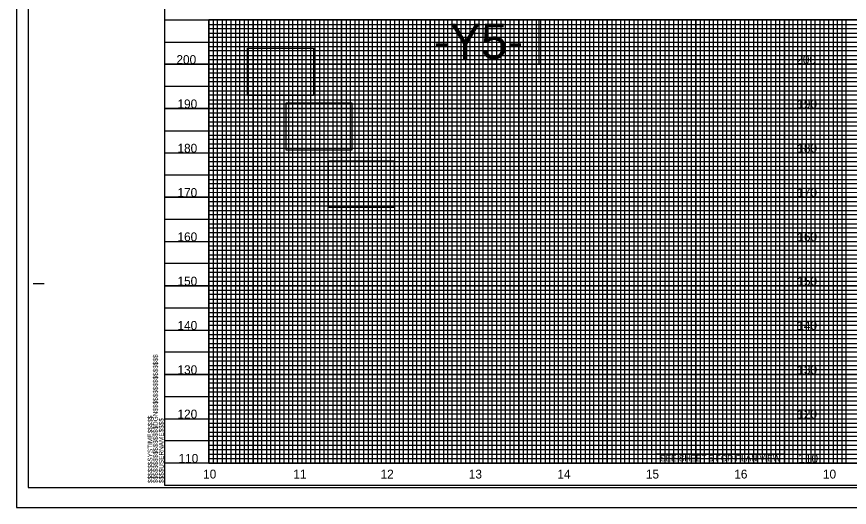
# Model space of a CAD drawing. Extents: x 1779926 to 1781626, y 618464 to 619564.
# Drawn here: x 1779926 to 1780866, y 618464 to 619018 of the extents above; entities that cross this region are included whole.
import ezdxf

# ---------------------------------------------------------------- set-up
doc = ezdxf.new("R2010")
doc.units = 0
for name, color, linetype in [('Exist Vertical Profile Horizontal Axis Label Major', 7, 'Continuous'), ('Exist Vertical Profile Vertical Axis Label', 7, 'Continuous'), ('Prop DSN Text', 7, 'Continuous'), ('Prop Grid Mask', 7, 'Continuous'), ('Sheet DOT Grid CELL', 7, 'Continuous'), ('Sheet Layout Profile Border Port 2', 7, 'Continuous'), ('Sheet Plot Border Inside CELL', 7, 'Continuous'), ('Sheet Plot Border Outside CELL', 7, 'Continuous'), ('Sheet Profile CELL', 7, 'Continuous'), ('Sheet Profile Grid Major CELL', 7, 'Continuous'), ('Sheet Profile Grid Middle CELL', 7, 'Continuous'), ('Sheet Profile Grid Minor CELL', 7, 'Continuous')]:
    doc.layers.add(name, color=color, linetype=linetype)

msp = doc.modelspace()

# ---------------------------------------------------------------- linework, layer by layer
at = {"layer": 'Prop Grid Mask'}
for points in [[(1780516.03, 619014.19), (1780393.09, 619014.19), (1780393.09, 618964.19), (1780516.03, 618964.19)], [(1780792.96, 619014.19), (1780842.96, 619014.19), (1780842.96, 618514.19), (1780792.96, 618514.19)], [(1780186.83, 618982.35), (1780261.08, 618982.35), (1780261.08, 618928.78), (1780186.83, 618928.78)], [(1780230.36, 618920.62), (1780304.61, 618920.62), (1780304.61, 618867.04), (1780230.36, 618867.04)], [(1780278.13, 618855.26), (1780352.38, 618855.26), (1780352.38, 618802.59), (1780278.13, 618802.59)], [(1780792.96, 618524.19), (1780647.96, 618524.19), (1780647.96, 618514.19), (1780792.96, 618514.19)]]:
    msp.add_lwpolyline(points, close=True, dxfattribs=at)
at = {"layer": 'Sheet DOT Grid CELL'}
for p, q in [((1780092.96, 619014.19), (1781592.85, 619014.19)), ((1780142.96, 619014.19), (1780142.96, 618514.19)), ((1780192.96, 619014.19), (1780192.96, 618514.19)), ((1780242.96, 619014.19), (1780242.96, 618514.19)), ((1780292.96, 619014.19), (1780292.96, 618514.19)), ((1780342.96, 619014.19), (1780342.96, 618514.19)), ((1780392.96, 619014.19), (1780392.96, 618514.19)), ((1780442.96, 619014.19), (1780442.96, 618514.19)), ((1780492.96, 619014.19), (1780492.96, 618514.19)), ((1780542.96, 619014.19), (1780542.96, 618514.19)), ((1780592.96, 619014.19), (1780592.96, 618514.19)), ((1780642.96, 619014.19), (1780642.96, 618514.19)), ((1780692.96, 619014.19), (1780692.96, 618514.19)), ((1780742.96, 619014.19), (1780742.96, 618514.19)), ((1780792.96, 619014.19), (1780792.96, 618514.19)), ((1780842.96, 619014.19), (1780842.96, 618514.19)), ((1780092.96, 618964.19), (1781592.85, 618964.19)), ((1780092.96, 618914.19), (1781592.85, 618914.19)), ((1780092.96, 618864.19), (1781592.85, 618864.19)), ((1780092.96, 618814.19), (1781592.85, 618814.19)), ((1780092.96, 618764.19), (1781592.85, 618764.19)), ((1780092.96, 618714.19), (1781592.85, 618714.19)), ((1780092.96, 618664.19), (1781592.85, 618664.19)), ((1780092.96, 618614.19), (1781592.85, 618614.19)), ((1780092.96, 618564.19), (1781592.85, 618564.19))]:
    msp.add_line(p, q, dxfattribs=at)
at = {"layer": 'Sheet Layout Profile Border Port 2'}
msp.add_lwpolyline([(1780142.96, 619014.19), (1781542.96, 619014.19), (1781542.96, 618514.19), (1780142.96, 618514.19)], close=True, dxfattribs=at)
msp.add_lwpolyline([(1781442.96, 619014.19), (1780142.96, 619014.19), (1780142.96, 618514.19), (1781542.96, 618514.19), (1781542.96, 619014.19)], dxfattribs=at)
at = {"layer": 'Sheet Plot Border Inside CELL'}
msp.add_lwpolyline([(1779938.96, 618486.64), (1781605.46, 618486.64), (1781605.46, 619541.74), (1779938.96, 619541.74)], close=True, dxfattribs=at)
at = {"layer": 'Sheet Plot Border Outside CELL'}
msp.add_lwpolyline([(1779925.96, 618464.19), (1781625.96, 618464.19), (1781625.96, 619564.19), (1779925.96, 619564.19)], close=True, dxfattribs=at)
at = {"layer": 'Sheet Profile CELL'}
for p, q in [((1780092.96, 619014.19), (1781592.96, 619014.19)), ((1779944.46, 618716.69), (1779956.96, 618716.69)), ((1781592.96, 618514.19), (1780092.96, 618514.19)), ((1780092.96, 618489.19), (1781592.96, 618489.19)), ((1780092.96, 618489.19), (1780092.96, 618489.19)), ((1780092.96, 618489.19), (1780092.96, 618489.19)), ((1780092.96, 618489.19), (1780092.96, 618489.19)), ((1780092.96, 618489.19), (1780092.96, 618489.19)), ((1780092.96, 618489.19), (1780092.96, 618489.19)), ((1780092.96, 618489.19), (1780092.96, 618489.19)), ((1780092.96, 618489.19), (1780092.96, 618489.19))]:
    msp.add_line(p, q, dxfattribs=at)
msp.add_lwpolyline([(1781592.96, 619539.19), (1780092.96, 619539.19), (1780092.96, 618489.19), (1781592.96, 618489.19)], close=True, dxfattribs=at)
msp.add_lwpolyline([(1780130.46, 618489.19), (1780130.46, 618489.19)], dxfattribs=at)
at = {"layer": 'Sheet Profile Grid Major CELL'}
for p, q in [((1780592.96, 619014.19), (1780642.96, 619014.19)), ((1780692.96, 619014.19), (1780742.96, 619014.19)), ((1780792.96, 619014.19), (1780842.96, 619014.19)), ((1780092.96, 618514.19), (1780092.96, 618514.19))]:
    msp.add_line(p, q, dxfattribs=at)
for points in [[(1780142.96, 619014.19), (1780142.96, 618514.19), (1780192.96, 618514.19), (1780192.96, 619014.19), (1780242.96, 619014.19), (1780242.96, 618514.19), (1780292.96, 618514.19), (1780292.96, 619014.19), (1780342.96, 619014.19), (1780342.96, 618514.19), (1780392.96, 618514.19), (1780392.96, 619014.19), (1780442.96, 619014.19), (1780442.96, 618514.19), (1780492.96, 618514.19), (1780492.96, 619014.19), (1780542.96, 619014.19), (1780542.96, 618514.19), (1780592.96, 618514.19), (1780592.96, 619014.19), (1780642.96, 619014.19), (1780642.96, 618514.19), (1780692.96, 618514.19), (1780692.96, 619014.19), (1780742.96, 619014.19), (1780742.96, 618514.19), (1780792.96, 618514.19), (1780792.96, 619014.19), (1780842.96, 619014.19), (1780842.96, 618514.19), (1780892.96, 618514.19)], [(1781592.96, 618964.19), (1780092.96, 618964.19)], [(1781592.96, 618914.19), (1780092.96, 618914.19), (1780092.96, 618864.19), (1781592.96, 618864.19)], [(1781592.96, 618814.19), (1780092.96, 618814.19), (1780092.96, 618764.19), (1781592.96, 618764.19)], [(1781592.96, 618714.19), (1780092.96, 618714.19), (1780092.96, 618664.19), (1781592.96, 618664.19)], [(1781592.96, 618614.19), (1780092.96, 618614.19), (1780092.96, 618614.19), (1780092.96, 618564.19), (1781592.96, 618564.19)], [(1781592.96, 618514.19), (1780092.96, 618514.19)]]:
    msp.add_lwpolyline(points, dxfattribs=at)
at = {"layer": 'Sheet Profile Grid Middle CELL'}
for points in [[(1780117.96, 619014.19), (1780167.96, 619014.19), (1780167.96, 618514.19), (1780217.96, 618514.19), (1780217.96, 619014.19), (1780267.96, 619014.19), (1780267.96, 618514.19), (1780317.96, 618514.19), (1780317.96, 619014.19), (1780367.96, 619014.19), (1780367.96, 618514.19), (1780417.96, 618514.19), (1780417.96, 619014.19), (1780467.96, 619014.19), (1780467.96, 618514.19), (1780517.96, 618514.19), (1780517.96, 619014.19), (1780567.96, 619014.19), (1780567.96, 618514.19), (1780617.96, 618514.19), (1780617.96, 619014.19), (1780667.96, 619014.19), (1780667.96, 618514.19), (1780717.96, 618514.19), (1780717.96, 618514.19), (1780717.96, 619014.19), (1780767.96, 619014.19), (1780767.96, 618514.19), (1780817.96, 618514.19), (1780817.96, 619014.19), (1780867.96, 619014.19)], [(1780092.96, 618989.19), (1781592.96, 618989.19)], [(1781592.96, 618939.19), (1780092.96, 618939.19), (1780092.96, 618889.19), (1781592.96, 618889.19)], [(1781592.96, 618839.19), (1780092.96, 618839.19), (1780092.96, 618789.19), (1781592.96, 618789.19)], [(1781592.96, 618739.19), (1780092.96, 618739.19), (1780092.96, 618689.19), (1781592.96, 618689.19)], [(1781592.96, 618639.19), (1780092.96, 618639.19), (1780092.96, 618589.19), (1781592.96, 618589.19)], [(1781592.96, 618539.19), (1780092.96, 618539.19)]]:
    msp.add_lwpolyline(points, dxfattribs=at)
at = {"layer": 'Sheet Profile Grid Minor CELL'}
for p, q in [((1780142.96, 619009.19), (1781542.96, 619009.19)), ((1781542.96, 619004.19), (1780142.96, 619004.19)), ((1780142.96, 618999.19), (1781542.96, 618999.19)), ((1781542.96, 618994.19), (1780142.96, 618994.19)), ((1780142.96, 618984.19), (1781542.96, 618984.19)), ((1781542.96, 618979.19), (1780142.96, 618979.19)), ((1780142.96, 618974.19), (1781542.96, 618974.19)), ((1781542.96, 618969.19), (1780142.96, 618969.19)), ((1780142.96, 618959.19), (1781542.96, 618959.19)), ((1781542.96, 618954.19), (1780142.96, 618954.19)), ((1780142.96, 618949.19), (1781542.96, 618949.19)), ((1781542.96, 618944.19), (1780142.96, 618944.19)), ((1780142.96, 618934.19), (1781542.96, 618934.19)), ((1781542.96, 618929.19), (1780142.96, 618929.19)), ((1780142.96, 618924.19), (1781542.96, 618924.19)), ((1781542.96, 618919.19), (1780142.96, 618919.19)), ((1780142.96, 618909.19), (1781542.96, 618909.19)), ((1781542.96, 618904.19), (1780142.96, 618904.19)), ((1780142.96, 618899.19), (1781542.96, 618899.19)), ((1781542.96, 618894.19), (1780142.96, 618894.19)), ((1780142.96, 618884.19), (1781542.96, 618884.19)), ((1781542.96, 618879.19), (1780142.96, 618879.19)), ((1780142.96, 618874.19), (1781542.96, 618874.19)), ((1781542.96, 618869.19), (1780142.96, 618869.19)), ((1780142.96, 618859.19), (1781542.96, 618859.19)), ((1781542.96, 618854.19), (1780142.96, 618854.19)), ((1780142.96, 618849.19), (1781542.96, 618849.19)), ((1781542.96, 618844.19), (1780142.96, 618844.19)), ((1780142.96, 618834.19), (1781542.96, 618834.19)), ((1781542.96, 618829.19), (1780142.96, 618829.19)), ((1780142.96, 618824.19), (1781542.96, 618824.19)), ((1781542.96, 618819.19), (1780142.96, 618819.34)), ((1780142.96, 618809.19), (1781542.96, 618809.19)), ((1781542.96, 618804.19), (1780142.96, 618804.19)), ((1780142.96, 618799.19), (1781542.96, 618799.19)), ((1781542.96, 618794.19), (1780142.96, 618794.19)), ((1780142.96, 618784.19), (1781542.96, 618784.19)), ((1781542.96, 618779.19), (1780142.96, 618779.19)), ((1780142.96, 618774.19), (1781542.96, 618774.19)), ((1781542.96, 618769.19), (1780142.96, 618769.19)), ((1780142.96, 618759.19), (1781542.96, 618759.19)), ((1781542.96, 618754.19), (1780142.96, 618754.19)), ((1780142.96, 618749.19), (1781542.96, 618749.19)), ((1781542.96, 618744.19), (1780142.96, 618744.19)), ((1780142.96, 618734.19), (1781542.96, 618734.19)), ((1781542.96, 618729.19), (1780142.96, 618729.19)), ((1780142.96, 618724.19), (1781542.96, 618724.19)), ((1781542.96, 618719.19), (1780142.96, 618719.19)), ((1780142.96, 618709.19), (1781542.96, 618709.19)), ((1781542.96, 618704.19), (1780142.96, 618704.19)), ((1780142.96, 618699.19), (1781542.96, 618699.19)), ((1781542.96, 618694.19), (1780142.96, 618694.19)), ((1780142.96, 618684.19), (1781542.96, 618684.19)), ((1781542.96, 618679.19), (1780142.96, 618679.19)), ((1780142.96, 618674.19), (1781542.96, 618674.19)), ((1781542.96, 618669.19), (1780142.96, 618669.19)), ((1780142.96, 618659.19), (1781542.96, 618659.19)), ((1781542.96, 618654.19), (1780142.96, 618654.19)), ((1780142.96, 618649.19), (1781542.96, 618649.19)), ((1781542.96, 618644.19), (1780142.96, 618644.19)), ((1780142.96, 618634.19), (1781542.96, 618634.19)), ((1781542.96, 618629.19), (1780142.96, 618629.19)), ((1780142.96, 618624.19), (1781542.96, 618624.19)), ((1781542.96, 618619.19), (1780142.96, 618619.19)), ((1780142.96, 618609.19), (1781542.96, 618609.19)), ((1781542.96, 618604.19), (1780142.96, 618604.19)), ((1780142.96, 618599.19), (1781542.96, 618599.19)), ((1781542.96, 618594.19), (1780142.96, 618594.19)), ((1780142.96, 618584.19), (1781542.96, 618584.19)), ((1781542.96, 618579.19), (1780142.96, 618579.19)), ((1780142.96, 618574.19), (1781542.96, 618574.19)), ((1781542.96, 618569.19), (1780142.96, 618569.19)), ((1780142.96, 618559.19), (1781542.96, 618559.19)), ((1781542.96, 618554.19), (1780142.96, 618554.19)), ((1780142.96, 618549.19), (1781542.96, 618549.19)), ((1781542.96, 618544.19), (1780142.96, 618544.19)), ((1780142.96, 618534.19), (1781542.96, 618534.19)), ((1781542.96, 618529.19), (1780142.96, 618529.19)), ((1780142.96, 618524.19), (1781542.96, 618524.19)), ((1780142.96, 618519.19), (1781542.96, 618519.19))]:
    msp.add_line(p, q, dxfattribs=at)
for points in [[(1780142.96, 619014.19), (1780147.96, 619014.19), (1780147.96, 618514.19), (1780152.96, 618514.19), (1780152.96, 619014.19), (1780157.96, 619014.19), (1780157.96, 618514.19), (1780162.96, 618514.19), (1780162.96, 619014.19), (1780172.96, 619014.19), (1780172.96, 618514.19), (1780177.96, 618514.19), (1780177.96, 619014.19), (1780182.96, 619014.19), (1780182.96, 618514.19), (1780187.96, 618514.19), (1780197.96, 618514.19), (1780202.96, 618514.19), (1780202.96, 619014.19), (1780207.96, 619014.19), (1780207.96, 618514.19), (1780212.96, 618514.19), (1780212.96, 619014.19), (1780222.96, 619014.19), (1780222.96, 618514.19), (1780227.96, 618514.19), (1780227.96, 619014.19), (1780232.96, 619014.19), (1780232.96, 618514.19), (1780237.96, 618514.19), (1780237.96, 619014.19), (1780247.96, 619014.19), (1780247.96, 618514.19), (1780252.96, 618514.19), (1780252.96, 619014.19), (1780257.96, 619014.19), (1780257.96, 618514.19), (1780262.96, 618514.19), (1780262.96, 619014.19), (1780272.96, 619014.19), (1780272.96, 618514.19), (1780277.96, 618514.19), (1780277.96, 619014.19), (1780282.96, 619014.19), (1780282.96, 618514.19), (1780287.96, 618514.19), (1780287.96, 619014.19), (1780297.96, 619014.19), (1780297.96, 618514.19), (1780302.96, 618514.19), (1780302.96, 619014.19), (1780307.96, 619014.19), (1780307.96, 618514.19), (1780312.96, 618514.19), (1780312.96, 619014.19), (1780322.96, 619014.19), (1780322.96, 618514.19), (1780327.96, 618514.19), (1780327.96, 619014.19), (1780332.96, 619014.19), (1780332.96, 618514.19), (1780337.96, 618514.19), (1780337.96, 619014.19), (1780347.96, 619014.19), (1780347.96, 618514.19), (1780352.96, 618514.19), (1780352.96, 619014.19), (1780357.96, 619014.19), (1780357.96, 618514.19)], [(1780187.96, 618514.19), (1780187.96, 619014.19), (1780197.96, 619014.19), (1780197.96, 618514.19)], [(1780357.96, 618514.19), (1780362.96, 618514.19), (1780362.96, 619014.19), (1780372.96, 619014.19), (1780372.96, 618514.19), (1780377.96, 618514.19), (1780377.96, 619014.19), (1780382.96, 619014.19), (1780382.96, 618514.19), (1780387.96, 618514.19), (1780387.96, 619014.19), (1780397.96, 619014.19), (1780397.96, 618514.19), (1780402.96, 618514.19), (1780402.96, 619014.19), (1780407.96, 619014.19), (1780407.96, 618514.19), (1780412.96, 618514.19), (1780412.96, 619014.19), (1780422.96, 619014.19), (1780422.96, 618514.19), (1780427.96, 618514.19), (1780427.96, 619014.19), (1780432.96, 619014.19), (1780432.96, 618514.19), (1780437.96, 618514.19), (1780437.96, 619014.19), (1780447.96, 619014.19), (1780447.96, 618514.19), (1780452.96, 618514.19), (1780452.96, 619014.19), (1780457.96, 619014.19), (1780457.96, 618514.19), (1780462.96, 618514.19), (1780462.96, 619014.19), (1780472.96, 619014.19), (1780472.96, 618514.19), (1780477.96, 618514.19), (1780477.96, 619014.19), (1780482.96, 619014.19), (1780482.96, 618514.19), (1780487.96, 618514.19), (1780487.96, 619014.19), (1780497.96, 619014.19), (1780497.96, 618514.19), (1780502.96, 618514.19), (1780502.96, 619014.19), (1780507.96, 619014.19), (1780507.96, 618514.19), (1780512.96, 618514.19), (1780512.96, 619014.19), (1780522.96, 619014.19), (1780522.96, 618514.19), (1780527.96, 618514.19), (1780527.96, 619014.19), (1780532.96, 619014.19), (1780532.96, 618514.19), (1780537.96, 618514.19), (1780537.96, 619014.19), (1780547.96, 619014.19), (1780547.96, 618514.19), (1780552.96, 618514.19), (1780552.96, 619014.19), (1780557.96, 619014.19), (1780557.96, 618514.19), (1780562.96, 618514.19), (1780562.96, 619014.19), (1780572.96, 619014.19), (1780572.96, 618514.19), (1780577.96, 618514.19), (1780577.96, 619014.19), (1780582.96, 619014.19), (1780582.96, 618514.19), (1780587.96, 618514.19), (1780587.96, 619014.19), (1780597.96, 619014.19), (1780597.96, 618514.19), (1780602.96, 618514.19), (1780602.96, 619014.19), (1780607.96, 619014.19), (1780607.96, 618514.19), (1780612.96, 618514.19), (1780612.96, 619014.19), (1780622.96, 619014.19), (1780622.96, 618514.19), (1780627.96, 618514.19), (1780627.96, 619014.19), (1780632.96, 619014.19), (1780632.96, 618514.19), (1780637.96, 618514.19), (1780637.96, 619014.19), (1780647.96, 619014.19), (1780647.96, 618514.19), (1780652.96, 618514.19), (1780652.96, 619014.19), (1780657.96, 619014.19), (1780657.96, 618514.19), (1780662.96, 618514.19), (1780662.96, 619014.19), (1780672.96, 619014.19)], [(1780672.96, 619014.19), (1780672.96, 618514.19), (1780677.96, 618514.19), (1780677.96, 619014.19), (1780682.96, 619014.19), (1780682.96, 618514.19), (1780687.96, 618514.19), (1780687.96, 619014.19), (1780697.96, 619014.19), (1780697.96, 618514.19), (1780702.96, 618514.19), (1780702.96, 619014.19), (1780707.96, 619014.19), (1780707.96, 618514.19), (1780712.96, 618514.19), (1780712.96, 619014.19), (1780722.96, 619014.19), (1780722.96, 618514.19), (1780727.96, 618514.19), (1780727.96, 619014.19), (1780732.96, 619014.19), (1780732.96, 618514.19), (1780737.96, 618514.19), (1780737.96, 619014.19), (1780747.96, 619014.19), (1780747.96, 618514.19), (1780752.96, 618514.19), (1780752.96, 619014.19), (1780757.96, 619014.19), (1780757.96, 618514.19), (1780762.96, 618514.19), (1780762.96, 619014.19), (1780772.96, 619014.19), (1780772.96, 618514.19), (1780777.96, 618514.19), (1780777.96, 619014.19), (1780782.96, 619014.19), (1780782.96, 618514.19), (1780787.96, 618514.19), (1780787.96, 619014.19), (1780797.96, 619014.19), (1780797.96, 618514.19), (1780797.96, 618514.19), (1780802.96, 618514.19), (1780802.96, 619014.19), (1780807.96, 619014.19), (1780807.96, 618514.19), (1780812.96, 618514.19), (1780812.96, 619014.19), (1780822.96, 619014.19), (1780822.96, 618514.19), (1780827.96, 618514.19), (1780827.96, 619014.19), (1780832.96, 619014.19), (1780832.96, 618514.19), (1780837.96, 618514.19), (1780837.96, 619014.19), (1780847.96, 619014.19), (1780847.96, 618514.19), (1780852.96, 618514.19), (1780852.96, 619014.19), (1780857.96, 619014.19), (1780857.96, 618514.19), (1780862.96, 618514.19), (1780862.96, 619014.19), (1780872.96, 619014.19)]]:
    msp.add_lwpolyline(points, dxfattribs=at)

# ---------------------------------------------------------------- texts
at = {"layer": 'Exist Vertical Profile Horizontal Axis Label Major'}
for s, p in [('10', (1780136.54, 618496.69)), ('11', (1780238.38, 618496.69)), ('12', (1780336.93, 618496.69)), ('13', (1780436.61, 618496.69)), ('14', (1780536.66, 618496.69)), ('15', (1780636.59, 618496.69)), ('16', (1780736.42, 618496.69)), ('10', (1780836.54, 618496.69))]:
    msp.add_text(s, height=10, dxfattribs=at).set_placement(p)
at = {"layer": 'Exist Vertical Profile Vertical Axis Label'}
for s, p in [('200', (1780106.39, 618964.44)), ('200', (1780806.39, 618964.44)), ('190', (1780107.59, 618914.44)), ('190', (1780807.59, 618914.44)), ('180', (1780107.59, 618864.44)), ('180', (1780807.59, 618864.44)), ('170', (1780107.59, 618814.44)), ('170', (1780807.59, 618814.44)), ('160', (1780107.59, 618764.44)), ('160', (1780807.59, 618764.44)), ('150', (1780107.59, 618714.44)), ('150', (1780807.59, 618714.44)), ('140', (1780107.59, 618664.44)), ('140', (1780807.59, 618664.44)), ('130', (1780107.59, 618614.44)), ('130', (1780807.59, 618614.44)), ('120', (1780107.59, 618564.44)), ('120', (1780807.59, 618564.44)), ('110', (1780108.79, 618514.44)), ('110', (1780808.79, 618514.44))]:
    msp.add_text(s, height=10, dxfattribs=at).set_placement(p)
at = {"layer": 'Prop DSN Text'}
for s, height, p in [('-Y5-', 40, (1780397.01, 618970.14)), ('SEE SHEET 5 FOR PLAN VIEW', 7, (1780652.54, 618516.14))]:
    msp.add_text(s, height=height, dxfattribs=at).set_placement(p)
at = {"layer": 'Sheet Profile CELL'}
for s, p in [('$$$$$$$$$$$$$$$$DGN$$$$$$$$$$$$$$$$', (1780085.32, 618491.57)), ('$$$$$$SYSTIME$$$$$', (1780079.27, 618491.57)), ('$$$$USERNAME$$$$', (1780091.9, 618491.58))]:
    msp.add_text(s, height=5.25, rotation=90, dxfattribs=at).set_placement(p)

doc.saveas('drawing.dxf')
